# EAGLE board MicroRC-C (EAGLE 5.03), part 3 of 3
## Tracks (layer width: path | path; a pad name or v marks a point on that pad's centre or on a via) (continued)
SPI_MOSI  (via drill 0.41) (continued)
  Top 0.178: v95.25,39.21 95.25,39.82 | 95.25,39.82 U8.4 | 57.31,38.89 94.3,38.89 94.61,39.21 94.64,39.21 | 94.64,39.21 v95.25,39.21 | v97.47,39.21 98.08,39.21 | 98.08,39.21 99.06,39.21 99.38,39.53 118.27,39.53 118.75,40 118.75,40.35 | U9.2 118.75,41.57 | 118.75,40.35 v118.75,40.96 | v118.75,40.96 118.75,41.57 | 57.31,38.89 | v56.83,38.42 57.26,38.85 | 57.26,38.85 57.31,38.89 | U2.12 52.01,21.01 50.8,22.22 50.8,31.14 | 50.8,31.14 v50.8,31.75 | 95.25,39.82 94.98,39.38 v95.25,39.21 | 95.25,39.82 95.52,39.38 v95.25,39.21 | 94.64,39.21 95.08,38.94 v95.25,39.21 | 94.64,39.21 95.08,39.48 v95.25,39.21 | 50.8,31.14 51.07,31.58 v50.8,31.75 | 50.8,31.14 50.53,31.58 v50.8,31.75 | 57.26,38.85 56.76,38.73 v56.83,38.42 | 57.26,38.85 57.14,38.34 v56.83,38.42 | 98.08,39.21 97.64,39.48 v97.47,39.21 | 98.08,39.21 97.64,38.94 v97.47,39.21 | 118.75,40.35 119.02,40.79 v118.75,40.96 | 118.75,40.35 118.47,40.79 v118.75,40.96 | 118.75,41.57 118.47,41.12 v118.75,40.96 | 118.75,41.57 119.02,41.12 v118.75,40.96
  Bottom 0.178: v95.25,39.21 95.86,39.21 | 95.86,39.21 96.86,39.21 | 96.86,39.21 v97.47,39.21 | 56.22,38.42 53.66,38.42 53.34,38.1 53.34,32.7 53.02,32.38 52.07,32.38 51.44,31.75 51.41,31.75 | 56.22,38.42 v56.83,38.42 | v50.8,31.75 51.41,31.75 | v118.75,40.96 119.36,40.96 | 119.36,40.96 122.24,40.96 123.19,40 J2.12 | 95.86,39.21 95.42,39.48 v95.25,39.21 | 95.86,39.21 95.42,38.94 v95.25,39.21 | 51.41,31.75 50.97,32.02 v50.8,31.75 | 51.41,31.75 50.97,31.48 v50.8,31.75 | 56.22,38.42 56.67,38.15 v56.83,38.42 | 56.22,38.42 56.67,38.69 v56.83,38.42 | 96.86,39.21 97.31,38.94 v97.47,39.21 | 96.86,39.21 97.31,39.48 v97.47,39.21 | 119.36,40.96 118.91,41.23 v118.75,40.96 | 119.36,40.96 118.91,40.69 v118.75,40.96
SPI_SCK  (via drill 0.41)
  Top 0.178: 96.52,38.42 U8.3 | 96.52,38.42 58.74,38.42 56.95,36.63 | 96.52,38.42 99.06,38.42 99.69,39.05 119.72,39.05 | 119.72,39.05 v120.33,39.05 | v120.33,36.51 120.33,35.9 | 120.33,35.9 120.33,35.24 120.02,34.92 U9.28 | v56.52,36.19 56.95,36.63 | v50.01,30.64 50.01,30.03 | 50.01,30.03 50.01,22.07 51.21,20.86 U2.11 51.21,17.37 51.59,16.99 51.59,15.72 52.07,15.24 53.98,15.24 54.29,14.92 R4.2 | 56.95,36.63 56.44,36.5 v56.52,36.19 | 56.95,36.63 56.82,36.12 v56.52,36.19 | 50.01,30.03 50.28,30.47 v50.01,30.64 | 50.01,30.03 49.73,30.47 v50.01,30.64 | 120.33,35.9 120.6,36.35 v120.33,36.51 | 120.33,35.9 120.06,36.35 v120.33,36.51 | 119.72,39.05 120.17,38.78 v120.33,39.05 | 119.72,39.05 120.17,39.32 v120.33,39.05
  Bottom 0.178: v120.33,39.05 120.33,38.44 | 120.33,38.44 120.33,37.46 | v50.01,30.64 50.62,30.64 | 50.62,30.64 51.28,30.64 52.23,31.59 56.04,31.59 56.52,32.07 56.52,35.58 | 56.52,35.58 v56.52,36.19 | 120.33,37.46 120.33,37.12 | 120.33,37.12 v120.33,36.51 | 120.33,37.46 J2.10 | 56.52,35.58 56.79,36.03 v56.52,36.19 | 56.52,35.58 56.24,36.03 v56.52,36.19 | 50.62,30.64 50.17,30.91 v50.01,30.64 | 50.62,30.64 50.17,30.37 v50.01,30.64 | 120.33,37.12 120.06,36.68 v120.33,36.51 | 120.33,37.12 120.6,36.68 v120.33,36.51 | 120.33,38.44 120.6,38.89 v120.33,39.05 | 120.33,38.44 120.06,38.89 v120.33,39.05
SPI_SS  (via drill 0.41)
  Top 0.178: U2.33 55.21,39.97 56.2,40.96 56.2,46.04 55.88,46.35 53.63,46.35 | 53.63,46.35 v53.02,46.35 | 53.63,46.35 53.19,46.63 v53.02,46.35 | 53.63,46.35 53.19,46.08 v53.02,46.35
  Bottom 0.178: J2.16 123.03,45.08 122.08,46.04 119.38,46.04 117.47,47.94 117.47,60.64 115.25,62.86 60.01,62.86 53.34,56.2 53.34,47.47 53.02,47.15 53.02,46.96 | v53.02,46.35 53.02,46.96 | 53.02,46.96 52.75,46.52 v53.02,46.35 | 53.02,46.96 53.29,46.52 v53.02,46.35
SS_ISD  (via drill 0.41)
  Top 0.178: 52.39,30.03 52.39,23.65 55.21,20.83 U2.16 | 52.39,30.03 v52.39,30.64 | v57.78,36.19 58.22,36.63 | 58.22,36.63 59.53,37.94 99.38,37.94 100.01,38.58 118.9,38.58 119.22,38.26 120.97,38.26 121.28,38.58 121.28,42.23 120.81,42.7 U9.1 | U9.1 120.02,42.54 | U9.1 | 52.39,30.03 52.66,30.47 v52.39,30.64 | 52.39,30.03 52.12,30.47 v52.39,30.64 | 58.22,36.63 57.71,36.5 v57.78,36.19 | 58.22,36.63 58.09,36.12 v57.78,36.19
  Bottom 0.178: 57.78,35.58 57.78,31.43 56.99,30.64 53,30.64 | 57.78,35.58 v57.78,36.19 | v52.39,30.64 53,30.64 | 53,30.64 52.55,30.91 v52.39,30.64 | 53,30.64 52.55,30.37 v52.39,30.64 | 57.78,35.58 58.06,36.03 v57.78,36.19 | 57.78,35.58 57.51,36.03 v57.78,36.19
SS_MX828  (via drill 0.41)
  Top 0.178: 57.31,39.85 92.39,39.85 92.71,40.16 U8.6 | 57.31,39.85 | v50.16,33.18 49.55,33.18 | 49.55,33.18 49.53,33.18 49.21,32.86 49.21,21.91 50.41,20.71 U2.10 | v56.83,40.32 57.26,39.89 | 57.26,39.89 57.31,39.85 | 57.26,39.89 57.14,40.4 v56.83,40.32 | 57.26,39.89 56.76,40.01 v56.83,40.32 | 49.55,33.18 50,32.91 v50.16,33.18 | 49.55,33.18 50,33.45 v50.16,33.18
  Bottom 0.178: 56.22,40.32 52.7,40.32 52.07,39.69 52.07,34.45 51.75,34.13 51.12,34.13 50.6,33.61 | 56.22,40.32 v56.83,40.32 | v50.16,33.18 50.6,33.61 | 56.22,40.32 56.67,40.05 v56.83,40.32 | 56.22,40.32 56.67,40.59 v56.83,40.32 | 50.6,33.61 50.09,33.49 v50.16,33.18 | 50.6,33.61 50.47,33.1 v50.16,33.18
TCK
  Top 0.178: JP1.1 57.47,4.29 57.15,3.97 45.4,3.97 44.77,4.6 44.77,13.97 44.13,14.6 RN1.1 41.91,16.99 41.12,17.78 31.27,17.78 30.96,18.1 30.96,27.94 31.27,28.26 39.37,28.26 40.41,27.22 U2.57
TDI
  Top 0.178: JP1.9 67.63,3.02 67.15,2.54 44.77,2.54 43.18,4.13 43.18,9.52 42.86,9.84 34.61,9.84 | U2.54 41.41,29.69 30.64,29.69 29.53,28.57 29.53,17.14 30.32,16.35 34.29,16.35 34.61,16.03 34.61,14.6 | 34.61,14.6 RN1.4 | 34.61,14.6 34.61,9.84 | R12.1 34.61,7.94 34.61,9.84
TDO  (via drill 0.41)
  Top 0.178: JP1.3 60.01,3.81 59.21,3.02 45.09,3.02 43.81,4.29 43.81,12.38 43.5,12.7 39.37,12.7 | U2.55 40.55,28.82 40.16,29.21 30.8,29.21 30,28.42 30,17.46 30.64,16.83 39.05,16.83 39.37,16.51 RN1.3 39.37,12.7 | 39.37,12.7 36.51,12.7 36.2,12.38 36.2,12.04 | 36.2,12.04 v36.2,11.43 | 36.2,12.04 35.92,11.59 v36.2,11.43 | 36.2,12.04 36.47,11.59 v36.2,11.43
  Top 0.254: v34.29,6.35 34.29,5.74 | 34.29,5.74 R14.1 | 34.29,5.74 34.54,6.22 v34.29,6.35 | 34.29,5.74 34.04,6.22 v34.29,6.35
  Bottom 0.178: 34.29,6.96 34.29,11.11 34.61,11.43 35.59,11.43 | 34.29,6.96 v34.29,6.35 | v36.2,11.43 35.59,11.43 | 34.29,6.96 34.02,6.52 v34.29,6.35 | 34.29,6.96 34.56,6.52 v34.29,6.35 | 35.59,11.43 36.03,11.16 v36.2,11.43 | 35.59,11.43 36.03,11.7 v36.2,11.43
TMS
  Top 0.178: JP1.5 62.55,6.35 62.23,6.67 59.21,6.67 58.74,6.19 58.74,3.97 58.26,3.49 45.24,3.49 44.29,4.44 44.29,12.7 43.66,13.33 40.96,13.33 40.64,13.65 RN1.2 40.64,16.67 40.01,17.3 30.96,17.3 30.48,17.78 30.48,28.26 30.96,28.73 39.85,28.73 40.56,28.02 U2.56
TX_AUDIO  (via drill 0.41)
  Top 0.254: X3.7 144.46,55.88 145.1,55.24 145.1,49.21 143.83,47.94 143.83,40.93 | v143.83,20 143.83,20.61 | 143.83,20.61 143.83,39.71 | 143.83,39.71 v143.83,40.32 | v143.83,40.32 143.83,40.93 | C52.2 133.06,13.65 | 133.06,13.65 v133.67,13.65 | v141.92,40.32 141.31,40.32 | 141.31,40.32 R61.2 | 133.06,13.65 133.54,13.4 v133.67,13.65 | 133.06,13.65 133.54,13.9 v133.67,13.65 | 143.83,20.61 143.58,20.13 v143.83,20 | 143.83,20.61 144.08,20.13 v143.83,20 | 143.83,39.71 144.08,40.19 v143.83,40.32 | 143.83,39.71 143.58,40.19 v143.83,40.32 | 143.83,40.93 143.58,40.45 v143.83,40.32 | 143.83,40.93 144.08,40.45 v143.83,40.32 | 141.31,40.32 141.79,40.07 v141.92,40.32 | 141.31,40.32 141.79,40.57 v141.92,40.32
  Bottom 0.254: v133.67,13.65 134.1,14.08 | 134.1,14.08 134.62,14.6 142.88,14.6 143.83,15.56 143.83,19.39 | 143.83,19.39 v143.83,20 | J2.5 129.86,32.38 137.79,40.32 141.31,40.32 | v143.83,40.32 143.22,40.32 | 143.22,40.32 142.53,40.32 | 142.53,40.32 v141.92,40.32 | v141.92,40.32 141.31,40.32 | 134.1,14.08 133.58,13.92 v133.67,13.65 | 134.1,14.08 133.93,13.57 v133.67,13.65 | 143.83,19.39 144.08,19.87 v143.83,20 | 143.83,19.39 143.58,19.87 v143.83,20 | 143.22,40.32 143.7,40.07 v143.83,40.32 | 143.22,40.32 143.7,40.57 v143.83,40.32 | 142.53,40.32 142.05,40.57 v141.92,40.32 | 142.53,40.32 142.05,40.07 v141.92,40.32 | 141.31,40.32 141.79,40.07 v141.92,40.32 | 141.31,40.32 141.79,40.57 v141.92,40.32
  Bottom 0.61: X3.7 X3A.7
TX_TONE_OUT  (via drill 0.41)
  Top 0.254: v97.79,31.75 97.79,32.36 | 97.79,32.36 U8.23 | 104.78,24.76 102.55,24.76 C50.1 | v105.73,24.76 105.12,24.76 | 105.12,24.76 104.78,24.76 | 104.78,24.76 TP5.TP | 97.79,32.36 97.54,31.88 v97.79,31.75 | 97.79,32.36 98.04,31.88 v97.79,31.75 | 105.12,24.76 105.6,24.52 v105.73,24.76 | 105.12,24.76 105.6,25.01 v105.73,24.76
  Bottom 0.254: 97.79,31.14 97.79,25.4 98.42,24.76 105.12,24.76 | 97.79,31.14 v97.79,31.75 | 105.12,24.76 v105.73,24.76 | 97.79,31.14 98.04,31.62 v97.79,31.75 | 97.79,31.14 97.54,31.62 v97.79,31.75 | 105.12,24.76 105.6,24.52 v105.73,24.76 | 105.12,24.76 105.6,25.01 v105.73,24.76
VBATT  (via drill 0.41)
  Top 0.178: v45.56,48.1 46.17,48.1 | 46.17,48.1 56.36,48.1 56.83,48.58 D7.C | U2.59 42.61,25.62 42.86,25.88 42.86,26.38 | v42.86,26.99 42.86,26.38 | 46.17,48.1 45.73,48.37 v45.56,48.1 | 46.17,48.1 45.73,47.83 v45.56,48.1 | 42.86,26.38 43.13,26.82 v42.86,26.99 | 42.86,26.38 42.59,26.82 v42.86,26.99
  Top 0.406: R23.2 C20.1 R21.1 59.05,53.02 58.1,52.07 D7.C
  Bottom 0.178: 42.25,26.99 41.91,26.99 41.59,27.3 41.59,33.34 41.91,33.65 42.86,33.65 43.5,34.29 43.5,47.47 44.13,48.1 44.95,48.1 | 42.25,26.99 v42.86,26.99 | 44.95,48.1 v45.56,48.1 | 44.95,48.1 45.4,47.83 v45.56,48.1 | 44.95,48.1 45.4,48.37 v45.56,48.1 | 42.25,26.99 42.7,26.72 v42.86,26.99 | 42.25,26.99 42.7,27.26 v42.86,26.99
VEE_LCD
  Top 0.254: J1.3 27.94,33.65 28.89,32.7 28.89,16.83 30.16,15.56 33.02,15.56 33.66,14.92 33.66,10.16 33.02,9.52 30.8,9.52 30.48,9.21 R2.2
VREF  (via drill 0.41)
  Top 0.254: 119.7,9.21 U10.10 | 119.7,9.21 U10.5 | U10.14 U10.13 119.09,5.4 | v119.7,5.4 119.09,5.4 | v119.7,5.4 119.7,6.01 | 119.7,6.01 119.7,9.21 | R24.1 98.42,7.3 98.22,7.1 | v97.79,6.67 98.22,7.1 | U5.3 97.18,6.67 | 97.18,6.67 v97.79,6.67 | 119.09,5.4 119.57,5.15 v119.7,5.4 | 119.09,5.4 119.57,5.65 v119.7,5.4 | 119.7,6.01 119.45,5.53 v119.7,5.4 | 119.7,6.01 119.95,5.53 v119.7,5.4 | 98.22,7.1 97.7,6.93 v97.79,6.67 | 98.22,7.1 98.06,6.58 v97.79,6.67 | 97.18,6.67 97.66,6.42 v97.79,6.67 | 97.18,6.67 97.66,6.92 v97.79,6.67
  Bottom 0.254: 119.09,5.4 110.81,5.4 110.17,6.03 110.17,8.89 109.54,9.52 98.42,9.52 97.79,8.89 97.79,7.28 | 119.09,5.4 v119.7,5.4 | v97.79,6.67 97.79,7.28 | 119.09,5.4 119.57,5.15 v119.7,5.4 | 119.09,5.4 119.57,5.65 v119.7,5.4 | 97.79,7.28 97.54,6.8 v97.79,6.67 | 97.79,7.28 98.04,6.8 v97.79,6.67
VSQL  (via drill 0.41)
  Top 0.178: U2.61 41.41,23.97 44.16,23.97 | v44.77,23.97 44.16,23.97 | 44.16,23.97 44.6,23.7 v44.77,23.97 | 44.16,23.97 44.6,24.24 v44.77,23.97
  Top 0.254: R37.1 R31.1 82.55,16.83 82.55,18.57 | 82.55,18.57 82.55,20.48 | v88.9,44.45 88.9,43.84 | 88.9,43.84 U8.9 | 88.29,35.56 84.61,35.56 83.34,34.29 83.34,24.45 82.55,23.65 82.55,22.86 | 88.29,35.56 v88.9,35.56 | v76.52,18.57 77.13,18.57 | 77.13,18.57 82.55,18.57 | v76.52,18.57 76.52,19.18 | 76.52,19.18 76.52,20.48 C78.+ 75.56,20.48 | 82.55,22.86 TP3.TP | 82.55,20.48 D10.C | 82.55,20.48 82.55,22.86 | 77.13,18.57 76.65,18.82 v76.52,18.57 | 77.13,18.57 76.65,18.32 v76.52,18.57 | 76.52,19.18 76.27,18.7 v76.52,18.57 | 76.52,19.18 76.77,18.7 v76.52,18.57 | 88.9,43.84 89.15,44.32 v88.9,44.45 | 88.9,43.84 88.65,44.32 v88.9,44.45 | 88.29,35.56 88.77,35.31 v88.9,35.56 | 88.29,35.56 88.77,35.81 v88.9,35.56
  Bottom 0.178: 45.2,23.54 45.4,23.34 45.4,20.16 45.72,19.84 53.66,19.84 54.45,19.05 54.45,15.08 55.24,14.29 75.88,14.29 76.52,14.92 76.52,17.96 | 45.2,23.54 v44.77,23.97 | 76.52,17.96 v76.52,18.57 | 45.2,23.54 45.08,24.05 v44.77,23.97 | 45.2,23.54 44.69,23.66 v44.77,23.97 | 76.52,17.96 76.79,18.41 v76.52,18.57 | 76.52,17.96 76.25,18.41 v76.52,18.57
  Bottom 0.254: v88.9,35.56 88.9,36.17 | 88.9,36.17 88.9,43.84 | 88.9,43.84 v88.9,44.45 | 88.9,43.84 89.15,44.32 v88.9,44.45 | 88.9,43.84 88.65,44.32 v88.9,44.45 | 88.9,36.17 88.65,35.69 v88.9,35.56 | 88.9,36.17 89.15,35.69 v88.9,35.56
VTEMP  (via drill 0.41)
  Top 0.178: v43.66,24.76 | U2.60 41.41,24.76 43.05,24.76 | v43.66,24.76 43.05,24.76 | 43.05,24.76 43.49,24.49 v43.66,24.76 | 43.05,24.76 43.49,25.04 v43.66,24.76
  Top 0.254: R20.1 65.11,11.11 | 65.11,11.11 v65.72,11.11 | v65.72,11.11 66.33,11.11 | 66.33,11.11 C19.1 | C19.1 | C19.1 R22.2 | 65.11,11.11 65.59,10.86 v65.72,11.11 | 65.11,11.11 65.59,11.36 v65.72,11.11 | 66.33,11.11 65.85,11.36 v65.72,11.11 | 66.33,11.11 65.85,10.86 v65.72,11.11
  Bottom 0.178: 43.66,24.16 43.66,23.81 44.45,23.02 44.77,22.7 44.77,20 45.4,19.37 53.5,19.37 53.98,18.89 53.98,14.92 55.24,13.65 65.09,13.65 65.72,13.02 65.72,11.72 | 43.66,24.16 v43.66,24.76 | v65.72,11.11 65.72,11.72 | 43.66,24.16 43.93,24.6 v43.66,24.76 | 43.66,24.16 43.38,24.6 v43.66,24.76 | 65.72,11.72 65.45,11.28 v65.72,11.11 | 65.72,11.72 65.99,11.28 v65.72,11.11
XADC  (via drill 0.41)
  Top 0.178: U2.58 41.41,26.51 40.62,26.51 | v40.01,26.51 40.62,26.51 | 40.62,26.51 40.17,26.78 v40.01,26.51 | 40.62,26.51 40.17,26.24 v40.01,26.51
  Bottom 0.178: 40.01,27.12 40.01,33.65 40.64,34.29 42.55,34.29 42.86,34.61 42.86,54.29 45.09,56.51 49.85,56.51 58.74,65.41 116.52,65.41 120.02,61.91 120.02,50.48 120.33,50.16 J2.20 | 40.01,27.12 v40.01,26.51 | 40.01,27.12 39.73,26.68 v40.01,26.51 | 40.01,27.12 40.28,26.68 v40.01,26.51

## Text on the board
GROUND: KG4LNE
SUPPLY: KG4LNE
Bottom: REV-C | MICRO-RC | 3XX-100 | TP8 | MADE IN USA
tPlace: 1 | PTT | DGND | AGND | FAN | COS | GND | AGND | 12V | RX | 5V | TX | AUX | 8 | CPU | 3V | BKLITE | INPUT | LVL | LCD | PWR | MADE IN USA | EXPANSION I/O | RECEIVE | LVL | MICRO-RC | RECORD | LVL | SQUELCH | CAL | EMPH | FLAT | PLAY | LVL | OUTPUT | LVL | BEEP | LVL | 1 | 2 | ISP | JTAG | RS232 | CONTRAST
bRestrict: 12VDC | - | +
